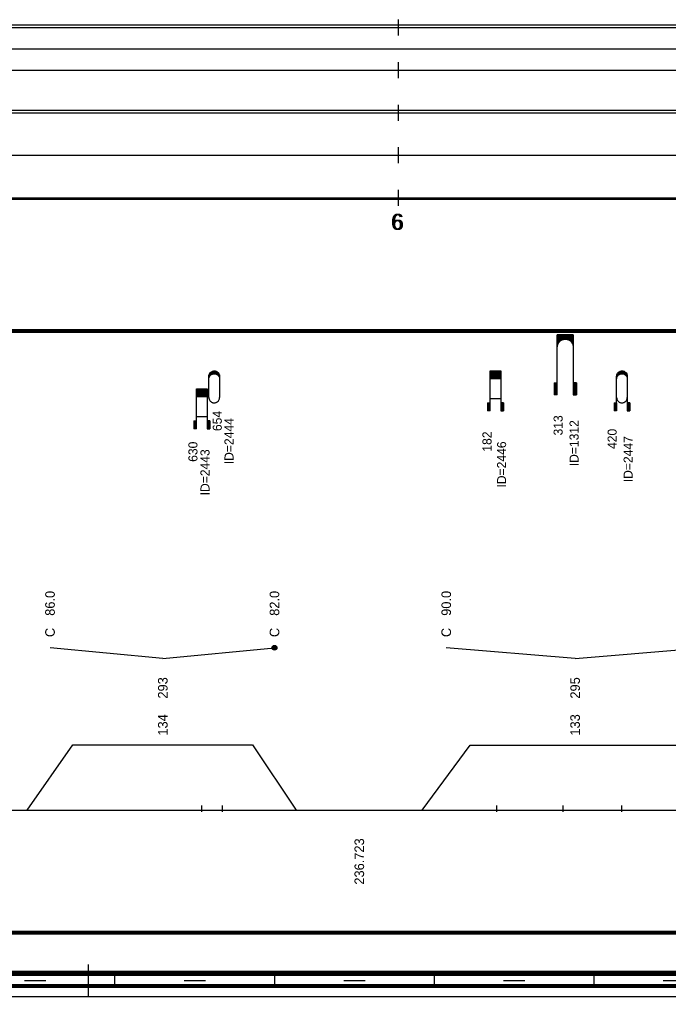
# Model space of a CAD drawing. Extents: x 2 to 10148, y 0 to 380.
# Drawn here: x 827.1 to 949, y 0 to 183.5 of the extents above; entities that cross this region are included whole.
import ezdxf

# ---------------------------------------------------------------- set-up
doc = ezdxf.new("R2010")
doc.units = 0
for name, color, linetype in [('CARA_S_OBJEKTY', 7, 'Continuous'), ('KRIV1_CARA', 7, 'Continuous'), ('KRIV1_TEXT', 7, 'Continuous'), ('OBJEKTY_TEXT', 7, 'Continuous'), ('OBJEKTY_TVAR', 7, 'Continuous'), ('RAM', 7, 'Continuous'), ('RYCHL_A', 7, 'Continuous'), ('RYCHL_B', 7, 'Continuous'), ('RYCHL_C', 7, 'Continuous'), ('RYCHL_RASTR', 7, 'Continuous'), ('RYCHL_STAN', 7, 'Continuous'), ('STAN_CARA', 7, 'Continuous')]:
    doc.layers.add(name, color=color, linetype=linetype)

msp = doc.modelspace()

# ---------------------------------------------------------------- linework, layer by layer
for p, q in [((861.27, 35.85), (861.27, 34.66)), ((865.11, 35.85), (865.11, 34.66)), ((916.7, 35.85), (916.7, 34.66)), ((929.16, 35.85), (929.16, 34.66)), ((940.16, 35.85), (940.16, 34.66))]:
    msp.add_line(p, q)
at = {"layer": 'CARA_S_OBJEKTY'}
for p, q in [((631.22, 125.25), (1245.39, 125.25)), ((631.22, 125), (1245.39, 125)), ((631.22, 124.75), (1245.39, 124.75))]:
    msp.add_line(p, q, dxfattribs=at)
at = {"layer": 'KRIV1_CARA'}
for p, q in [((828.49, 35), (837.09, 47.27)), ((837.09, 47.27), (870.86, 47.27)), ((870.86, 47.27), (879.06, 35)), ((902.73, 35), (911.73, 47.2)), ((911.73, 47.2), (951.15, 47.2)), ((631.22, 35), (1245.39, 35))]:
    msp.add_line(p, q, dxfattribs=at)
at = {"layer": 'KRIV1_TEXT'}
for p, q in [((853.98, 63.5), (832.79, 65.5)), ((853.98, 63.5), (874.96, 65.5)), ((931.44, 63.5), (907.23, 65.5)), ((931.44, 63.5), (955.6, 65.5))]:
    msp.add_line(p, q, dxfattribs=at)
for radius in [0.45, 0.3, 0.15]:
    msp.add_circle((874.96, 65.5), radius, dxfattribs=at)
at = {"layer": 'OBJEKTY_TVAR'}
for p, q in [((928.1, 113), (928.1, 124.25)), ((931.1, 124.25), (928.1, 124.25)), ((928.1, 124.17), (931.1, 124.17)), ((928.1, 124.1), (931.1, 124.1)), ((928.1, 124.02), (931.1, 124.02)), ((928.1, 123.95), (931.1, 123.95)), ((928.1, 123.87), (931.1, 123.87)), ((928.1, 123.8), (931.1, 123.8)), ((928.1, 123.72), (931.1, 123.72)), ((928.1, 123.65), (931.1, 123.65)), ((928.1, 123.57), (931.1, 123.57)), ((928.1, 123.5), (931.1, 123.5)), ((928.1, 123.42), (929.26, 123.42)), ((928.1, 123.35), (929.02, 123.35)), ((928.1, 123.27), (928.87, 123.27)), ((928.1, 123.2), (928.75, 123.2)), ((928.1, 123.12), (928.65, 123.12)), ((928.1, 123.05), (928.56, 123.05)), ((928.1, 122.97), (928.49, 122.97)), ((928.43, 122.9), (928.56, 123.05)), ((928.56, 123.05), (928.64, 123.12)), ((928.64, 123.12), (928.74, 123.19)), ((928.74, 123.19), (928.87, 123.27)), ((928.87, 123.27), (929.02, 123.35)), ((929.02, 123.35), (929.26, 123.42)), ((929.26, 123.42), (929.47, 123.46)), ((929.47, 123.46), (929.72, 123.46)), ((929.72, 123.46), (929.86, 123.44)), ((929.86, 123.44), (929.94, 123.42)), ((929.94, 123.42), (931.1, 123.42)), ((929.94, 123.42), (930.18, 123.35)), ((930.18, 123.35), (931.1, 123.35)), ((930.18, 123.35), (930.33, 123.27)), ((930.33, 123.27), (931.1, 123.27)), ((930.33, 123.27), (930.45, 123.2)), ((930.45, 123.2), (931.1, 123.2)), ((930.45, 123.2), (930.55, 123.12)), ((930.55, 123.12), (931.1, 123.12)), ((930.55, 123.12), (930.64, 123.05)), ((930.64, 123.05), (931.1, 123.05)), ((930.64, 123.05), (930.71, 122.97)), ((930.71, 122.97), (931.1, 122.97)), ((930.71, 122.97), (930.77, 122.9)), ((931.1, 124.25), (931.1, 113)), ((928.1, 122.9), (928.43, 122.9)), ((928.1, 122.82), (928.37, 122.82)), ((928.1, 122.75), (928.32, 122.75)), ((928.1, 122.67), (928.28, 122.67)), ((928.1, 122.6), (928.24, 122.6)), ((928.1, 122.52), (928.21, 122.52)), ((928.1, 122.45), (928.18, 122.45)), ((928.1, 122.37), (928.16, 122.37)), ((928.1, 122.3), (928.14, 122.3)), ((928.1, 122.22), (928.12, 122.22)), ((928.1, 122.15), (928.11, 122.15)), ((928.1, 121.97), (928.11, 122.11)), ((928.11, 122.11), (928.13, 122.28)), ((928.13, 122.28), (928.18, 122.46)), ((928.18, 122.46), (928.25, 122.61)), ((928.25, 122.61), (928.32, 122.75)), ((928.32, 122.75), (928.43, 122.9)), ((930.77, 122.9), (931.09, 122.9)), ((930.77, 122.9), (930.83, 122.82)), ((930.83, 122.82), (931.1, 122.82)), ((930.83, 122.82), (930.92, 122.67)), ((930.88, 122.75), (931.1, 122.75)), ((930.92, 122.67), (931.1, 122.67)), ((930.92, 122.67), (930.99, 122.52)), ((930.96, 122.6), (931.1, 122.6)), ((930.99, 122.52), (931.1, 122.52)), ((930.99, 122.52), (931.04, 122.37)), ((931.02, 122.45), (931.1, 122.45)), ((931.04, 122.37), (931.1, 122.37)), ((931.04, 122.37), (931.08, 122.22)), ((931.06, 122.3), (931.1, 122.3)), ((931.08, 122.22), (931.1, 122.22)), ((931.08, 122.22), (931.1, 121.97)), ((931.09, 122.15), (931.1, 122.15)), ((863.29, 117.43), (863.41, 117.47)), ((863.34, 117.45), (863.96, 117.45)), ((863.41, 117.47), (863.55, 117.49)), ((863.55, 117.49), (863.66, 117.5)), ((863.66, 117.5), (863.79, 117.49)), ((863.79, 117.49), (863.92, 117.46)), ((863.92, 117.46), (864.03, 117.43)), ((915.48, 110), (915.48, 117.5)), ((915.48, 117.5), (917.48, 117.5)), ((915.48, 117.45), (917.48, 117.45)), ((917.48, 117.5), (917.48, 110)), ((939.89, 117.43), (940.01, 117.47)), ((939.94, 117.45), (940.56, 117.45)), ((940.01, 117.47), (940.15, 117.49)), ((940.15, 117.49), (940.26, 117.5)), ((940.26, 117.5), (940.39, 117.49)), ((940.39, 117.49), (940.52, 117.46)), ((940.52, 117.46), (940.63, 117.43)), ((862.65, 116.5), (862.66, 116.65)), ((862.65, 116.55), (862.83, 116.55)), ((862.65, 112.5), (862.65, 116.5)), ((862.65, 116.5), (862.8, 116.5)), ((862.65, 116.45), (862.77, 116.45)), ((862.65, 116.4), (862.74, 116.4)), ((862.65, 116.35), (862.72, 116.35)), ((862.65, 116.3), (862.7, 116.3)), ((862.65, 116.25), (862.69, 116.25)), ((862.65, 116.2), (862.68, 116.2)), ((862.65, 116.15), (862.67, 116.15)), ((862.65, 115.98), (862.66, 116.13)), ((862.65, 116.1), (862.66, 116.1)), ((862.66, 116.65), (862.7, 116.81)), ((862.66, 116.65), (862.91, 116.65)), ((862.66, 116.6), (862.87, 116.6)), ((862.66, 116.13), (862.7, 116.28)), ((862.67, 116.7), (862.96, 116.7)), ((862.68, 116.75), (863.02, 116.75)), ((862.7, 116.81), (862.76, 116.95)), ((862.7, 116.8), (863.08, 116.8)), ((862.7, 116.28), (862.76, 116.43)), ((862.71, 116.85), (863.16, 116.85)), ((862.73, 116.9), (863.27, 116.9)), ((862.76, 116.95), (862.82, 117.06)), ((862.76, 116.95), (863.42, 116.95)), ((862.76, 116.43), (862.82, 116.53)), ((862.78, 117), (864.52, 117)), ((862.81, 117.05), (864.49, 117.05)), ((862.82, 117.06), (862.91, 117.18)), ((862.82, 116.53), (862.91, 116.65)), ((862.85, 117.1), (864.45, 117.1)), ((862.89, 117.15), (864.41, 117.15)), ((862.91, 117.18), (863, 117.26)), ((862.91, 116.65), (863, 116.74)), ((862.94, 117.2), (864.36, 117.2)), ((862.99, 117.25), (864.31, 117.25)), ((863, 117.26), (863.13, 117.35)), ((863, 116.74), (863.13, 116.83)), ((863.05, 117.3), (864.25, 117.3)), ((863.12, 117.35), (864.18, 117.35)), ((863.13, 117.35), (863.26, 117.42)), ((863.13, 116.83), (863.26, 116.9)), ((863.21, 117.4), (864.09, 117.4)), ((863.26, 117.42), (863.29, 117.43)), ((863.26, 116.9), (863.29, 116.91)), ((863.29, 116.91), (863.41, 116.95)), ((863.41, 116.95), (863.55, 116.97)), ((863.55, 116.97), (863.66, 116.98)), ((863.66, 116.98), (863.79, 116.97)), ((863.79, 116.97), (863.92, 116.94)), ((863.88, 116.95), (864.54, 116.95)), ((863.92, 116.94), (864.03, 116.9)), ((864.03, 117.43), (864.14, 117.37)), ((864.03, 116.9), (864.57, 116.9)), ((864.03, 116.9), (864.14, 116.85)), ((864.14, 117.37), (864.21, 117.32)), ((864.14, 116.85), (864.59, 116.85)), ((864.14, 116.85), (864.21, 116.8)), ((864.21, 117.32), (864.36, 117.21)), ((864.21, 116.8), (864.36, 116.68)), ((864.22, 116.8), (864.6, 116.8)), ((864.28, 116.75), (864.62, 116.75)), ((864.34, 116.7), (864.63, 116.7)), ((864.36, 117.21), (864.44, 117.11)), ((864.36, 116.68), (864.44, 116.59)), ((864.39, 116.65), (864.64, 116.65)), ((864.43, 116.6), (864.64, 116.6)), ((864.44, 117.11), (864.53, 116.98)), ((864.44, 116.59), (864.53, 116.46)), ((864.47, 116.55), (864.65, 116.55)), ((864.5, 116.5), (864.65, 116.5)), ((864.53, 116.98), (864.57, 116.89)), ((864.53, 116.46), (864.57, 116.37)), ((864.53, 116.45), (864.65, 116.45)), ((864.56, 116.4), (864.65, 116.4)), ((864.57, 116.89), (864.61, 116.77)), ((864.57, 116.37), (864.61, 116.24)), ((864.58, 116.35), (864.65, 116.35)), ((864.6, 116.3), (864.65, 116.3)), ((864.61, 116.77), (864.64, 116.65)), ((864.61, 116.25), (864.65, 116.25)), ((864.61, 116.24), (864.64, 116.13)), ((864.62, 116.2), (864.65, 116.2)), ((864.63, 116.15), (864.65, 116.15)), ((864.64, 116.65), (864.65, 116.56)), ((864.64, 116.13), (864.65, 116.03)), ((864.64, 116.1), (864.65, 116.1)), ((864.65, 116.56), (864.65, 116.5)), ((864.65, 116.5), (864.65, 112.5)), ((864.65, 116.03), (864.65, 115.98)), ((915.48, 117.4), (917.48, 117.4)), ((915.48, 117.35), (917.48, 117.35)), ((915.48, 117.3), (917.48, 117.3)), ((915.48, 117.25), (917.48, 117.25)), ((915.48, 117.2), (917.48, 117.2)), ((915.48, 117.15), (917.48, 117.15)), ((915.48, 117.1), (917.48, 117.1)), ((915.48, 117.05), (917.48, 117.05)), ((915.48, 117), (917.48, 117)), ((915.48, 116.95), (917.48, 116.95)), ((915.48, 116.9), (917.48, 116.9)), ((915.48, 116.85), (917.48, 116.85)), ((915.48, 116.8), (917.48, 116.8)), ((915.48, 116.75), (917.48, 116.75)), ((915.48, 116.7), (917.48, 116.7)), ((915.48, 116.65), (917.48, 116.65)), ((915.48, 116.6), (917.48, 116.6)), ((915.48, 116.55), (917.48, 116.55)), ((915.48, 116.5), (917.48, 116.5)), ((915.48, 116.45), (917.48, 116.45)), ((915.48, 116.4), (917.48, 116.4)), ((915.48, 116.35), (917.48, 116.35)), ((915.48, 116.3), (917.48, 116.3)), ((915.48, 116.25), (917.48, 116.25)), ((915.48, 116.2), (917.48, 116.2)), ((915.48, 116.15), (917.48, 116.15)), ((915.48, 116.1), (917.48, 116.1)), ((915.48, 116.05), (917.48, 116.05)), ((939.25, 116.5), (939.26, 116.65)), ((939.25, 116.55), (939.43, 116.55)), ((939.25, 110), (939.25, 116.5)), ((939.25, 116.5), (939.4, 116.5)), ((939.25, 116.45), (939.37, 116.45)), ((939.25, 116.4), (939.34, 116.4)), ((939.25, 116.35), (939.32, 116.35)), ((939.25, 116.3), (939.3, 116.3)), ((939.25, 116.25), (939.29, 116.25)), ((939.25, 116.2), (939.28, 116.2)), ((939.25, 116.15), (939.27, 116.15)), ((939.25, 115.98), (939.26, 116.13)), ((939.25, 116.1), (939.26, 116.1)), ((939.26, 116.65), (939.3, 116.81)), ((939.26, 116.65), (939.51, 116.65)), ((939.26, 116.6), (939.47, 116.6)), ((939.26, 116.13), (939.3, 116.28)), ((939.27, 116.7), (939.56, 116.7)), ((939.28, 116.75), (939.62, 116.75)), ((939.3, 116.81), (939.36, 116.95)), ((939.3, 116.8), (939.68, 116.8)), ((939.3, 116.28), (939.36, 116.43)), ((939.31, 116.85), (939.76, 116.85)), ((939.33, 116.9), (939.87, 116.9)), ((939.36, 116.95), (939.42, 117.06)), ((939.36, 116.95), (940.02, 116.95)), ((939.36, 116.43), (939.42, 116.53)), ((939.38, 117), (941.12, 117)), ((939.41, 117.05), (941.09, 117.05)), ((939.42, 117.06), (939.51, 117.18)), ((939.42, 116.53), (939.51, 116.65)), ((939.45, 117.1), (941.05, 117.1)), ((939.49, 117.15), (941.01, 117.15)), ((939.51, 117.18), (939.6, 117.26)), ((939.51, 116.65), (939.6, 116.74)), ((939.54, 117.2), (940.96, 117.2)), ((939.59, 117.25), (940.91, 117.25)), ((939.6, 117.26), (939.73, 117.35)), ((939.6, 116.74), (939.73, 116.83)), ((939.65, 117.3), (940.85, 117.3)), ((939.72, 117.35), (940.78, 117.35)), ((939.73, 117.35), (939.86, 117.42)), ((939.73, 116.83), (939.86, 116.9)), ((939.81, 117.4), (940.69, 117.4)), ((939.86, 117.42), (939.89, 117.43)), ((939.86, 116.9), (939.89, 116.91)), ((939.89, 116.91), (940.01, 116.95)), ((940.01, 116.95), (940.15, 116.97)), ((940.15, 116.97), (940.26, 116.98)), ((940.26, 116.98), (940.39, 116.97)), ((940.39, 116.97), (940.52, 116.94)), ((940.48, 116.95), (941.14, 116.95)), ((940.52, 116.94), (940.63, 116.9)), ((940.63, 117.43), (940.74, 117.37)), ((940.63, 116.9), (940.74, 116.85)), ((940.63, 116.9), (941.17, 116.9)), ((940.74, 117.37), (940.81, 117.32)), ((940.74, 116.85), (941.19, 116.85)), ((940.74, 116.85), (940.81, 116.8)), ((940.81, 117.32), (940.96, 117.21)), ((940.81, 116.8), (940.96, 116.68)), ((940.82, 116.8), (941.2, 116.8)), ((940.88, 116.75), (941.22, 116.75)), ((940.94, 116.7), (941.23, 116.7)), ((940.96, 117.21), (941.04, 117.11)), ((940.96, 116.68), (941.04, 116.59)), ((940.99, 116.65), (941.24, 116.65)), ((941.03, 116.6), (941.24, 116.6)), ((941.04, 117.11), (941.13, 116.98)), ((941.04, 116.59), (941.13, 116.46)), ((941.07, 116.55), (941.25, 116.55)), ((941.1, 116.5), (941.25, 116.5)), ((941.13, 116.98), (941.17, 116.89)), ((941.13, 116.46), (941.17, 116.37)), ((941.13, 116.45), (941.25, 116.45)), ((941.16, 116.4), (941.25, 116.4)), ((941.17, 116.89), (941.21, 116.77)), ((941.17, 116.37), (941.21, 116.24)), ((941.18, 116.35), (941.25, 116.35)), ((941.2, 116.3), (941.25, 116.3)), ((941.21, 116.77), (941.24, 116.65)), ((941.21, 116.25), (941.25, 116.25)), ((941.21, 116.24), (941.24, 116.13)), ((941.22, 116.2), (941.25, 116.2)), ((941.23, 116.15), (941.25, 116.15)), ((941.24, 116.65), (941.25, 116.56)), ((941.24, 116.13), (941.25, 116.03)), ((941.24, 116.1), (941.25, 116.1)), ((941.25, 116.56), (941.25, 116.5)), ((941.25, 116.5), (941.25, 110)), ((941.25, 116.03), (941.25, 115.98)), ((860.31, 106.62), (860.31, 114.12)), ((860.31, 114.12), (862.31, 114.12)), ((860.31, 114.07), (862.31, 114.07)), ((860.31, 114.02), (862.31, 114.02)), ((860.31, 113.97), (862.31, 113.97)), ((860.31, 113.92), (862.31, 113.92)), ((860.31, 113.87), (862.31, 113.87)), ((860.31, 113.82), (862.31, 113.82)), ((862.31, 114.12), (862.31, 106.62)), ((927.5, 115.25), (928.1, 115.25)), ((927.5, 115.25), (927.5, 113)), ((927.57, 115.25), (927.57, 113)), ((927.65, 115.25), (927.65, 113)), ((927.72, 115.25), (927.72, 113)), ((927.8, 115.25), (927.8, 113)), ((927.87, 115.25), (927.87, 113)), ((927.95, 115.25), (927.95, 113)), ((928.02, 115.25), (928.02, 113)), ((931.7, 115.25), (931.1, 115.25)), ((931.18, 115.25), (931.18, 113)), ((931.25, 115.25), (931.25, 113)), ((931.33, 115.25), (931.33, 113)), ((931.4, 115.25), (931.4, 113)), ((931.48, 115.25), (931.48, 113)), ((931.55, 115.25), (931.55, 113)), ((931.63, 115.25), (931.63, 113)), ((931.7, 115.25), (931.7, 113)), ((860.31, 113.77), (862.31, 113.77)), ((860.31, 113.72), (862.31, 113.72)), ((860.31, 113.67), (862.31, 113.67)), ((860.31, 113.62), (862.31, 113.62)), ((860.31, 113.57), (862.31, 113.57)), ((860.31, 113.52), (862.31, 113.52)), ((860.31, 113.47), (862.31, 113.47)), ((860.31, 113.42), (862.31, 113.42)), ((860.31, 113.37), (862.31, 113.37)), ((860.31, 113.32), (862.31, 113.32)), ((860.31, 113.27), (862.31, 113.27)), ((860.31, 113.22), (862.31, 113.22)), ((860.31, 113.17), (862.31, 113.17)), ((860.31, 113.12), (862.31, 113.12)), ((860.31, 113.07), (862.31, 113.07)), ((860.31, 113.02), (862.31, 113.02)), ((860.31, 112.97), (862.31, 112.97)), ((860.31, 112.92), (862.31, 112.92)), ((860.31, 112.87), (862.31, 112.87)), ((860.31, 112.82), (862.31, 112.82)), ((860.31, 112.77), (862.31, 112.77)), ((860.31, 112.72), (862.31, 112.72)), ((860.31, 112.67), (862.31, 112.67)), ((862.65, 112.5), (862.66, 112.35)), ((862.66, 112.35), (862.7, 112.2)), ((862.7, 112.2), (862.76, 112.05)), ((862.76, 112.05), (862.82, 111.95)), ((862.82, 111.95), (862.91, 111.83)), ((864.44, 111.9), (864.53, 112.02)), ((864.53, 112.02), (864.57, 112.11)), ((864.57, 112.11), (864.61, 112.24)), ((864.61, 112.24), (864.64, 112.35)), ((864.64, 112.35), (864.65, 112.45)), ((864.65, 112.45), (864.65, 112.5)), ((915.48, 112.31), (917.48, 112.31)), ((928.1, 113), (927.5, 113)), ((931.1, 113), (931.7, 113)), ((939.25, 112.5), (939.26, 112.35)), ((939.26, 112.35), (939.3, 112.2)), ((939.3, 112.2), (939.36, 112.05)), ((939.36, 112.05), (939.42, 111.95)), ((939.42, 111.95), (939.51, 111.83)), ((941.04, 111.9), (941.13, 112.02)), ((941.13, 112.02), (941.17, 112.11)), ((941.17, 112.11), (941.21, 112.24)), ((941.21, 112.24), (941.24, 112.35)), ((941.24, 112.35), (941.25, 112.45)), ((941.25, 112.45), (941.25, 112.5)), ((862.91, 111.83), (863, 111.74)), ((863, 111.74), (863.13, 111.65)), ((863.13, 111.65), (863.26, 111.58)), ((863.26, 111.58), (863.29, 111.57)), ((863.29, 111.57), (863.41, 111.53)), ((863.41, 111.53), (863.55, 111.51)), ((863.55, 111.51), (863.66, 111.5)), ((863.66, 111.5), (863.79, 111.51)), ((863.79, 111.51), (863.92, 111.54)), ((863.92, 111.54), (864.03, 111.58)), ((864.03, 111.58), (864.14, 111.63)), ((864.14, 111.63), (864.21, 111.68)), ((864.21, 111.68), (864.36, 111.8)), ((864.36, 111.8), (864.44, 111.9)), ((914.98, 111.5), (915.48, 111.5)), ((914.98, 111.5), (914.98, 110)), ((915.03, 111.5), (915.03, 110)), ((915.08, 111.5), (915.08, 110)), ((915.13, 111.5), (915.13, 110)), ((915.18, 111.5), (915.18, 110)), ((915.23, 111.5), (915.23, 110)), ((915.28, 111.5), (915.28, 110)), ((915.33, 111.5), (915.33, 110)), ((915.38, 111.5), (915.38, 110)), ((915.43, 111.5), (915.43, 110)), ((917.98, 111.5), (917.48, 111.5)), ((917.53, 111.5), (917.53, 110)), ((917.58, 111.5), (917.58, 110)), ((917.63, 111.5), (917.63, 110)), ((917.68, 111.5), (917.68, 110)), ((917.73, 111.5), (917.73, 110)), ((917.78, 111.5), (917.78, 110)), ((917.83, 111.5), (917.83, 110)), ((917.88, 111.5), (917.88, 110)), ((917.93, 111.5), (917.93, 110)), ((917.98, 111.5), (917.98, 110)), ((938.75, 111.5), (939.25, 111.5)), ((938.75, 111.5), (938.75, 110)), ((938.8, 111.5), (938.8, 110)), ((938.85, 111.5), (938.85, 110)), ((938.9, 111.5), (938.9, 110)), ((938.95, 111.5), (938.95, 110)), ((939, 111.5), (939, 110)), ((939.05, 111.5), (939.05, 110)), ((939.1, 111.5), (939.1, 110)), ((939.15, 111.5), (939.15, 110)), ((939.2, 111.5), (939.2, 110)), ((939.51, 111.83), (939.6, 111.74)), ((939.6, 111.74), (939.73, 111.65)), ((939.73, 111.65), (939.86, 111.58)), ((939.86, 111.58), (939.89, 111.57)), ((939.89, 111.57), (940.01, 111.53)), ((940.01, 111.53), (940.15, 111.51)), ((940.15, 111.51), (940.26, 111.5)), ((940.26, 111.5), (940.39, 111.51)), ((940.39, 111.51), (940.52, 111.54)), ((940.52, 111.54), (940.63, 111.58)), ((940.63, 111.58), (940.74, 111.63)), ((940.74, 111.63), (940.81, 111.68)), ((940.81, 111.68), (940.96, 111.8)), ((940.96, 111.8), (941.04, 111.9)), ((941.75, 111.5), (941.25, 111.5)), ((941.3, 111.5), (941.3, 110)), ((941.35, 111.5), (941.35, 110)), ((941.4, 111.5), (941.4, 110)), ((941.45, 111.5), (941.45, 110)), ((941.5, 111.5), (941.5, 110)), ((941.55, 111.5), (941.55, 110)), ((941.6, 111.5), (941.6, 110)), ((941.65, 111.5), (941.65, 110)), ((941.7, 111.5), (941.7, 110)), ((941.75, 111.5), (941.75, 110)), ((860.31, 108.93), (862.31, 108.93)), ((915.48, 110), (914.98, 110)), ((917.48, 110), (917.98, 110)), ((939.25, 110), (938.75, 110)), ((941.25, 110), (941.75, 110)), ((859.81, 108.12), (860.31, 108.12)), ((859.81, 108.12), (859.81, 106.62)), ((860.31, 106.62), (859.81, 106.62)), ((859.86, 108.12), (859.86, 106.62)), ((859.91, 108.12), (859.91, 106.62)), ((859.96, 108.12), (859.96, 106.62)), ((860.01, 108.12), (860.01, 106.62)), ((860.06, 108.12), (860.06, 106.62)), ((860.11, 108.12), (860.11, 106.62)), ((860.16, 108.12), (860.16, 106.62)), ((860.21, 108.12), (860.21, 106.62)), ((860.26, 108.12), (860.26, 106.62)), ((862.81, 108.12), (862.31, 108.12)), ((862.31, 106.62), (862.81, 106.62)), ((862.36, 108.12), (862.36, 106.62)), ((862.41, 108.12), (862.41, 106.62)), ((862.46, 108.12), (862.46, 106.62)), ((862.51, 108.12), (862.51, 106.62)), ((862.56, 108.12), (862.56, 106.62)), ((862.61, 108.12), (862.61, 106.62)), ((862.66, 108.12), (862.66, 106.62)), ((862.71, 108.12), (862.71, 106.62)), ((862.76, 108.12), (862.76, 106.62)), ((862.81, 108.12), (862.81, 106.62))]:
    msp.add_line(p, q, dxfattribs=at)
at = {"layer": 'RAM'}
for p, q in [((840, 0), (840, 6)), ((631.22, 4.75), (1245.39, 4.75)), ((631.22, 4.5), (1245.39, 4.5)), ((631.22, 4.25), (1245.39, 4.25)), ((631.22, 4), (1245.39, 4)), ((845, 2), (845, 4)), ((875, 2), (875, 4)), ((905, 2), (905, 4)), ((935, 2), (935, 4)), ((631.22, 2.25), (1245.39, 2.25)), ((631.22, 2), (1245.39, 2)), ((828, 3), (832, 3)), ((858, 3), (862, 3)), ((888, 3), (892, 3)), ((918, 3), (922, 3)), ((948, 3), (952, 3)), ((631.22, 1.75), (1245.39, 1.75)), ((631.22, 0), (1245.39, 0))]:
    msp.add_line(p, q, dxfattribs=at)
at = {"layer": 'RYCHL_A'}
msp.add_line((683.29, 166.5), (959.89, 166.5), dxfattribs=at)
at = {"layer": 'RYCHL_B'}
msp.add_line((776.13, 178), (967.19, 178), dxfattribs=at)
at = {"layer": 'RYCHL_C'}
msp.add_line((809.57, 182.5), (967.94, 182.5), dxfattribs=at)
at = {"layer": 'RYCHL_RASTR'}
for p, q in [((898.29, 180.5), (898.29, 183.5)), ((631.22, 182), (1245.39, 182)), ((898.29, 172.5), (898.29, 175.5)), ((631.22, 174), (1245.39, 174)), ((898.29, 164.5), (898.29, 167.5)), ((631.22, 166), (1245.39, 166)), ((631.22, 158), (1245.39, 158)), ((898.29, 156.5), (898.29, 159.5)), ((898.29, 148.5), (898.29, 151.5)), ((631.22, 150), (1245.39, 150)), ((631.22, 149.75), (1245.39, 149.75))]:
    msp.add_line(p, q, dxfattribs=at)
at = {"layer": 'STAN_CARA'}
for p, q in [((799.79, 12.25), (1245.39, 12.25)), ((799.79, 12), (1245.39, 12)), ((799.79, 12), (1245.39, 12)), ((799.79, 11.75), (1245.39, 11.75))]:
    msp.add_line(p, q, dxfattribs=at)

# ---------------------------------------------------------------- texts
at = {"layer": 'KRIV1_TEXT'}
for s, p in [('86.0', (833.69, 71.5)), ('82.0', (875.86, 71.5)), ('90.0', (908.13, 71.5)), ('C', (833.69, 67.5)), ('C', (875.86, 67.5)), ('C', (908.13, 67.5)), ('293', (854.88, 55.95)), ('295', (932.34, 55.95)), ('134', (854.88, 49)), ('133', (932.34, 49)), ('236.723', (891.8, 21))]:
    msp.add_text(s, height=1.8, rotation=90, dxfattribs=at).set_placement(p)
at = {"layer": 'OBJEKTY_TEXT'}
for s, p in [('654', (865.06, 106.2)), ('ID=2444', (867.27, 99.97)), ('313', (929.1, 105.37)), ('ID=1312', (932.1, 99.59)), ('420', (939.25, 102.83)), ('182', (915.74, 102.33)), ('ID=2447', (942.25, 96.59)), ('630', (860.49, 100.42)), ('ID=2446', (918.48, 95.59)), ('ID=2443', (862.76, 94.12))]:
    msp.add_text(s, height=1.7, rotation=90, dxfattribs=at).set_placement(p)
at = {"layer": 'RYCHL_STAN'}
for p in [(896.82, 144), (897.07, 144)]:
    msp.add_text('6', height=3, dxfattribs=at).set_placement(p)

doc.saveas('drawing.dxf')
